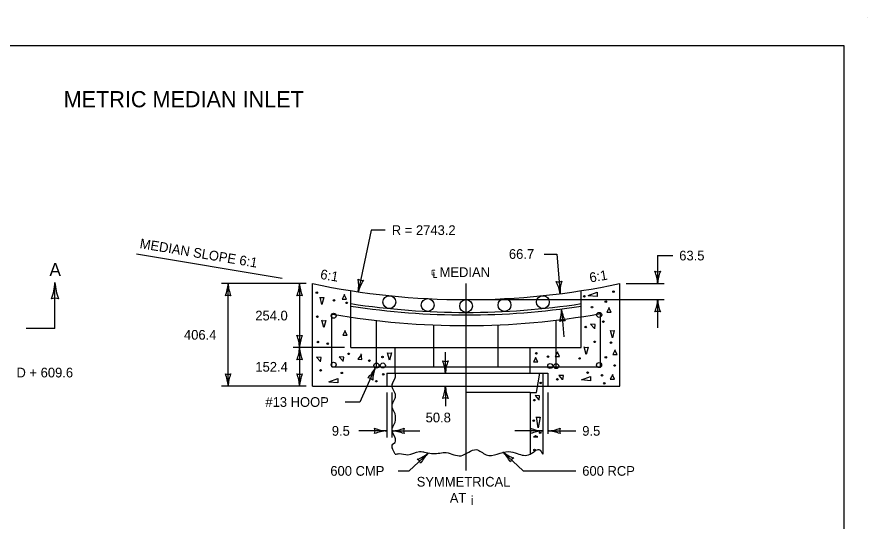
# Model space of a CAD drawing. Extents: x 49991.4 to 50021, y 49987.6 to 50011.4.
# Drawn here: x 50011.64 to 50016.9, y 49996.05 to 49999.18 of the extents above; entities that cross this region are included whole.
import ezdxf

# ---------------------------------------------------------------- set-up
doc = ezdxf.new("R2010")
doc.units = 0
for name, color, linetype in [('Level 1', 7, 'Continuous'), ('Level 2', 7, 'Continuous'), ('Level 3', 7, 'Continuous'), ('Level 4', 7, 'Continuous'), ('Level 5', 7, 'Continuous'), ('Level 6', 7, 'Continuous')]:
    doc.layers.add(name, color=color, linetype=linetype)

msp = doc.modelspace()

# ---------------------------------------------------------------- linework, layer by layer
at = {"layer": 'Level 1'}
for p, q in [((50016.9001, 49999.1756), (50016.9001, 49999.1756)), ((50013.4642, 49996.894), (50013.4642, 49997.5274)), ((50015.3641, 49996.894), (50015.3641, 49997.5274)), ((50013.7017, 49997.1316), (50013.7017, 49997.4839)), ((50015.1266, 49997.1316), (50015.1266, 49997.4839)), ((50014.7555, 49997.3617), (50014.7555, 49997.3617)), ((50013.5829, 49997.0127), (50013.5829, 49997.3383)), ((50015.2454, 49997.0127), (50015.2454, 49997.3419)), ((50013.8595, 49997.0127), (50013.8595, 49997.299)), ((50014.2144, 49997.0126), (50014.2144, 49997.271)), ((50014.612, 49997.0127), (50014.612, 49997.272)), ((50014.9718, 49997.0127), (50014.9718, 49997.3012)), ((50013.7017, 49997.1316), (50015.1266, 49997.1316)), ((50013.9747, 49996.9732), (50013.9747, 49997.1316)), ((50014.81, 49996.9732), (50014.81, 49997.1316)), ((50013.5829, 49997.0127), (50015.2454, 49997.0127)), ((50013.9242, 49996.9732), (50013.9242, 49996.894)), ((50013.9242, 49996.9732), (50013.9748, 49996.9732)), ((50013.9581, 49996.9107), (50013.9747, 49996.9441)), ((50013.9748, 49996.9732), (50014.8891, 49996.9732)), ((50014.8495, 49996.8544), (50014.8694, 49996.9732)), ((50014.8891, 49996.9732), (50014.8891, 49996.4721)), ((50014.8891, 49996.9732), (50014.9192, 49996.9732)), ((50014.9192, 49996.9732), (50014.9192, 49996.894)), ((50013.4642, 49996.894), (50013.9242, 49996.894)), ((50013.9747, 49996.848), (50013.9581, 49996.8813)), ((50014.9192, 49996.894), (50015.3641, 49996.894)), ((50014.81, 49996.8544), (50014.4141, 49996.8544)), ((50014.81, 49996.8544), (50014.81, 49996.4721)), ((50014.81, 49996.8544), (50014.8495, 49996.8544)), ((50013.9581, 49996.7853), (50013.9747, 49996.8187)), ((50013.9747, 49996.7227), (50013.9581, 49996.756)), ((50013.9581, 49996.6375), (50013.9747, 49996.6709)), ((50013.9747, 49996.5749), (50013.9581, 49996.6082)), ((50013.9581, 49996.5347), (50013.9747, 49996.5456)), ((50013.9747, 49996.4721), (50013.9581, 49996.5054))]:
    msp.add_line(p, q, dxfattribs=at)
msp.add_lwpolyline([(49999.3835, 49998.9992), (50016.7501, 49998.9992), (50016.7501, 49987.7988), (49999.3835, 49987.7988)], close=True, dxfattribs=at)
for points in [[(50013.6625, 49997.4608), (50013.6472, 49997.4322), (50013.6742, 49997.4322), (50013.6608, 49997.4592)], [(50015.1692, 49997.4541), (50015.2248, 49997.4744), (50015.2248, 49997.4474), (50015.1692, 49997.4525)], [(50013.5108, 49997.4407), (50013.5344, 49997.4424), (50013.5226, 49997.3986), (50013.5108, 49997.4441)], [(50015.2989, 49997.38), (50015.2838, 49997.3513), (50015.3108, 49997.3513), (50015.2973, 49997.3783)], [(50013.5825, 49997.3385), (50013.5853, 49997.3413), (50013.5855, 49997.3415)], [(50013.5226, 49997.2974), (50013.5462, 49997.2991), (50013.5344, 49997.2553), (50013.5226, 49997.3007)], [(50015.2097, 49997.2485), (50015.213, 49997.2755), (50015.1844, 49997.2772), (50015.2063, 49997.2519)], [(50013.6658, 49997.2367), (50013.6507, 49997.2081), (50013.6776, 49997.2081), (50013.6642, 49997.2351)], [(50015.3073, 49997.2351), (50015.3309, 49997.2368), (50015.3192, 49997.1929), (50015.3073, 49997.2385)], [(50013.7672, 49997.0891), (50013.7452, 49997.0604), (50013.7688, 49997.0587), (50013.7655, 49997.0924)], [(50013.9288, 49997.0968), (50013.9524, 49997.0986), (50013.9406, 49997.0547), (50013.9288, 49997.1002)], [(50014.9804, 49997.1052), (50014.9653, 49997.0767), (50014.9922, 49997.0767), (50014.9787, 49997.1036)], [(50015.1455, 49997.1322), (50015.1691, 49997.134), (50015.1574, 49997.0901), (50015.1455, 49997.1357)], [(50015.336, 49997.117), (50015.3208, 49997.0884), (50015.3478, 49997.0884), (50015.3343, 49997.1153)], [(50013.5142, 49997.0446), (50013.5175, 49997.0716), (50013.4889, 49997.0732), (50013.5108, 49997.048)], [(50013.654, 49997.0462), (50013.6574, 49997.0732), (50013.6287, 49997.0749), (50013.6507, 49997.0497)], [(50014.8456, 49997.0715), (50014.8305, 49997.0429), (50014.8574, 49997.0429), (50014.844, 49997.0698)], [(50013.5648, 49996.9198), (50013.6203, 49996.9401), (50013.6203, 49996.9131), (50013.5648, 49996.9182)], [(50015.0124, 49996.9316), (50015.0158, 49996.9586), (50014.9871, 49996.9602), (50015.009, 49996.935)], [(50015.1288, 49996.9333), (50015.1844, 49996.9536), (50015.1844, 49996.9267), (50015.1288, 49996.9317)], [(50015.3208, 49996.9653), (50015.3057, 49996.9367), (50015.3327, 49996.9367), (50015.3192, 49996.9637)], [(50014.8658, 49996.8069), (50014.8692, 49996.8339), (50014.8405, 49996.8356), (50014.8624, 49996.8103)], [(50014.849, 49996.7007), (50014.8726, 49996.7024), (50014.8608, 49996.6362), (50014.849, 49996.7041)], [(50014.8456, 49996.5872), (50014.8305, 49996.5811), (50014.8574, 49996.5811), (50014.844, 49996.5856)]]:
    msp.add_lwpolyline(points, dxfattribs=at)
for centre in [(50013.4906, 49997.471), (50015.3259, 49997.4777), (50013.5968, 49997.4238), (50013.676, 49997.4086), (50015.1456, 49997.4491), (50015.2787, 49997.4154), (50015.1928, 49997.3817), (50013.4939, 49997.3227), (50015.154, 49997.2587), (50015.2635, 49997.2924), (50013.4973, 49997.1659), (50013.558, 49997.1559), (50015.2096, 49997.1677), (50015.3107, 49997.1626), (50013.6878, 49997.0935), (50014.8489, 49997.0968), (50013.8159, 49997.0514), (50013.8968, 49997.0732), (50014.9202, 49997.076), (50015.1159, 49997.0648), (50015.2787, 49997.0716), (50013.5142, 49996.9907), (50015.3326, 49997.021), (50013.6456, 49996.9755), (50013.9018, 49996.9671), (50014.9787, 49996.9351), (50015.1658, 49996.9772), (50015.2551, 49996.9604), (50013.8594, 49996.924), (50014.8759, 49996.9131), (50015.2686, 49996.9115), (50014.8355, 49996.807), (50014.8321, 49996.6806), (50014.8725, 49996.6064), (50014.8372, 49996.4985)]:
    msp.add_circle(centre, 0.00476, dxfattribs=at)
for centre, major_axis, ratio, start_param, end_param in [((50014.4141, 50002.0379), (0, -4.6095), 0.99996, 6.075605, 6.490769), ((50014.4141, 50002.0379), (0, -4.6886), 0.99996, 6.130631, 6.435739), ((50014.4141, 50002.0323), (0, -4.6985), 0.99996, 6.130999, 6.435415), ((50014.4065, 50002.0353), (0, -4.7678), 0.99996, 6.110622, 6.460063), ((50013.9454, 49996.9587), (0, -0.0328), 0.99996, 1.107175, 2.034314), ((50013.9874, 49996.896), (0, 0.0328), 0.99996, 1.107223, 2.034348), ((50013.9454, 49996.8334), (0, -0.0328), 0.99996, 1.107175, 2.034314), ((50013.9874, 49996.7707), (0, 0.0328), 0.99996, 1.107223, 2.034348), ((50013.9454, 49996.6968), (0, -0.0579), 0.565735, 1.107175, 2.034314), ((50013.9874, 49996.6229), (0, 0.0328), 0.99996, 1.107223, 2.034348), ((50013.9454, 49996.5602), (0, -0.0328), 0.99996, 1.107175, 2.034314), ((50013.9874, 49996.5201), (0, 0.0328), 0.99996, 1.107223, 2.034348)]:
    msp.add_ellipse(centre, major_axis=major_axis, ratio=ratio, start_param=start_param, end_param=end_param, dxfattribs=at)
for centre, major_axis in [((50013.9392, 49997.4129), (0, 0.0396)), ((50014.1767, 49997.3949), (0, 0.0396)), ((50014.4141, 49997.3888), (0, 0.0396)), ((50014.6516, 49997.3949), (0, 0.0396)), ((50014.8891, 49997.4129), (0, 0.0396)), ((50013.5949, 49997.329), (0, 0.0156)), ((50015.2381, 49997.3341), (0, 0.0156)), ((50013.5949, 49997.0256), (0, 0.0156)), ((50015.2364, 49997.024), (0, 0.0156)), ((50013.8595, 49997.0206), (0, 0.0156)), ((50013.8991, 49997.0214), (0, 0.0156)), ((50014.9343, 49997.018), (0, 0.0156)), ((50014.9718, 49997.0172), (0, 0.0156))]:
    msp.add_ellipse(centre, major_axis=major_axis, ratio=0.99996, dxfattribs=at)
msp.add_spline([(50013.9747, 49996.4721), (50014.0004, 49996.4761), (50014.0537, 49996.4698), (50014.1257, 49996.4886), (50014.2104, 49996.4761), (50014.2917, 49996.4823), (50014.3826, 49996.4636), (50014.4766, 49996.5011), (50014.5385, 49996.4693), (50014.6771, 49996.4886), (50014.7303, 49996.4761), (50014.81, 49996.4721), (50014.865, 49996.5011), (50014.8891, 49996.4721)], degree=3, dxfattribs=at)
at = {"layer": 'Level 2'}
msp.add_line((50013.2773, 49997.5587), (50012.376, 49997.7095), dxfattribs=at)
at = {"layer": 'Level 3'}
for p, q in [((50013.8275, 49997.858), (50013.7472, 49997.4769)), ((50013.9145, 49997.858), (50013.8275, 49997.858)), ((50014.898, 49997.7104), (50014.9747, 49997.7104)), ((50014.9747, 49997.7104), (50014.9952, 49997.4652)), ((50015.5989, 49997.7008), (50015.5989, 49997.5274)), ((50015.5989, 49997.7008), (50015.6925, 49997.7008)), ((50013.4242, 49997.5274), (50012.9021, 49997.5274)), ((50012.9421, 49996.894), (50012.9421, 49997.5274)), ((50013.3839, 49997.5274), (50013.3839, 49997.1318)), ((50015.4041, 49997.5274), (50015.6389, 49997.5274)), ((50014.5141, 49997.4284), (50015.6389, 49997.4284)), ((50015.5989, 49997.4284), (50015.5989, 49997.255)), ((50015.0035, 49997.3709), (50015.0187, 49997.1981)), ((50013.6617, 49997.1316), (50013.3439, 49997.1316)), ((50013.3839, 49997.1318), (50013.3839, 49996.894)), ((50014.2861, 49996.9732), (50014.2861, 49997.1032)), ((50013.8524, 49997.0068), (50013.7574, 49996.7954)), ((50013.4242, 49996.894), (50012.9021, 49996.894)), ((50014.2861, 49996.894), (50014.2861, 49996.7697)), ((50013.9242, 49996.854), (50013.9242, 49996.5769)), ((50013.954, 49996.854), (50013.954, 49996.5769)), ((50014.9192, 49996.854), (50014.9192, 49996.5994)), ((50013.7574, 49996.7954), (50013.667, 49996.7954)), ((50013.9242, 49996.6169), (50013.7508, 49996.6169)), ((50013.954, 49996.6169), (50014.1274, 49996.6169)), ((50014.8891, 49996.6169), (50014.7157, 49996.6169)), ((50014.9192, 49996.6169), (50015.0926, 49996.6169)), ((50014.1797, 49996.48), (50014.0619, 49996.3694)), ((50014.1479, 49996.4889), (50014.1479, 49996.4865)), ((50014.6405, 49996.4878), (50014.7666, 49996.3694)), ((50013.994, 49996.3694), (50014.0619, 49996.3694)), ((50014.7666, 49996.3694), (50015.0926, 49996.3694))]:
    msp.add_line(p, q, dxfattribs=at)
for centre, radius, start, end in [((50013.1618, 49997.5366), 0.2223, 337.456, 357.6395), ((50013.6166, 49997.5389), 0.233, 182.8273, 202.0772), ((50013.7737, 49997.6024), 0.0548, 240.2517, 275.974), ((50013.5172, 49997.5136), 0.233, 350.9402, 10.19), ((50013.9627, 49997.4222), 0.2223, 145.5689, 165.7524), ((50014.9845, 49997.593), 0.0548, 256.9218, 292.6442), ((50014.7642, 49997.4343), 0.233, 7.6103, 26.8602), ((50015.2173, 49997.4746), 0.2223, 162.239, 182.4225), ((50013.3839, 49997.3992), 0.0548, 72.1388, 107.8612), ((50013.3839, 49997.2598), 0.0548, 252.1388, 287.8612), ((50013.1512, 49997.1201), 0.233, 2.8273, 22.0772), ((50013.606, 49997.1224), 0.2223, 157.456, 177.6395), ((50013.1618, 49997.1408), 0.2223, 337.456, 357.6395), ((50013.6166, 49997.1431), 0.233, 182.8273, 202.0772), ((50013.3839, 49997.0034), 0.0548, 72.1388, 107.8612), ((50013.6536, 49997.1062), 0.2223, 313.2474, 333.4309), ((50014.0694, 49996.9218), 0.233, 158.6187, 177.8686), ((50013.3839, 49997.0222), 0.0548, 252.1388, 287.8612), ((50013.1512, 49996.8825), 0.233, 2.8273, 22.0772), ((50013.606, 49996.8848), 0.2223, 157.456, 177.6395), ((50013.7998, 49996.8898), 0.0548, 47.9302, 83.6526), ((50013.9334, 49996.839), 0.2223, 247.456, 267.6395), ((50013.796, 49996.6169), 0.0548, 342.1388, 17.8612), ((50013.9425, 49996.8496), 0.233, 272.8273, 292.0772), ((50014.0822, 49996.6169), 0.0548, 162.1388, 197.8612), ((50014.8983, 49996.839), 0.2223, 247.456, 267.6395), ((50014.7609, 49996.6169), 0.0548, 342.1388, 17.8612), ((50014.9077, 49996.8496), 0.233, 272.8273, 292.0772), ((50015.0474, 49996.6169), 0.0548, 162.1388, 197.8612), ((50013.9357, 49996.3842), 0.233, 92.8273, 112.0772), ((50013.9448, 49996.3948), 0.2223, 67.456, 87.6395), ((50014.9006, 49996.3842), 0.233, 92.8273, 112.0772), ((50014.91, 49996.3948), 0.2223, 67.456, 87.6395)]:
    msp.add_arc(centre, radius, start, end, dxfattribs=at)
for centre, major_axis, start_param, end_param in [((50015.5989, 49997.6556), (0, -0.0548), 5.971449, 6.594922), ((50015.3662, 49997.5159), (0, 0.233), 4.761735, 5.097708), ((50015.821, 49997.5182), (0, 0.2223), 1.177329, 1.529598), ((50011.5748, 49997.5466), (0, -0.2964), 1.177329, 1.529598), ((50012.1813, 49997.5497), (0, -0.3107), 4.761735, 5.097708), ((50012.72, 49997.5366), (0, -0.2223), 1.177329, 1.529598), ((50013.1748, 49997.5389), (0, -0.233), 4.761735, 5.097708), ((50011.871, 49997.3634), (0, 0.073), 5.971449, 6.594922), ((50012.9421, 49997.3992), (0, 0.0548), 5.971449, 6.594922), ((50015.3768, 49997.4376), (0, -0.2223), 1.177329, 1.529598), ((50015.8316, 49997.4399), (0, -0.233), 4.761735, 5.097708), ((50014.7815, 49997.3592), (0, -0.2223), 1.271255, 1.623523), ((50015.2341, 49997.4042), (0, -0.233), 4.85566, 5.191633), ((50015.5989, 49997.3002), (0, 0.0548), 5.971449, 6.594922), ((50015.0155, 49997.2432), (0, 0.0548), 6.065374, 6.688847), ((50014.2861, 49997.1014), (0, -0.0548), 5.971449, 6.594922), ((50014.0534, 49996.9617), (0, 0.233), 4.761735, 5.097708), ((50014.5082, 49996.964), (0, 0.2223), 1.177329, 1.529598), ((50012.9421, 49997.0222), (0, -0.0548), 5.971449, 6.594922), ((50012.7094, 49996.8825), (0, 0.233), 4.761735, 5.097708), ((50013.1642, 49996.8848), (0, 0.2223), 1.177329, 1.529598), ((50014.064, 49996.9032), (0, -0.2223), 1.177329, 1.529598), ((50014.5188, 49996.9055), (0, -0.233), 4.761735, 5.097708), ((50014.2861, 49996.7658), (0, 0.0548), 5.971449, 6.594922), ((50014.0372, 49996.6507), (0, -0.2223), 0.343529, 0.695798), ((50014.3447, 49996.3154), (0, 0.233), 0.786342, 1.122315), ((50014.486, 49996.3279), (0, 0.2223), 5.162843, 5.515112), ((50014.7865, 49996.6694), (0, -0.233), 5.605656, 5.941629), ((50014.0848, 49996.3939), (0, 0.0548), 5.137648, 5.761121), ((50014.7363, 49996.4026), (0, 0.0548), 0.532185, 1.155658)]:
    msp.add_ellipse(centre, major_axis=major_axis, ratio=0.99996, start_param=start_param, end_param=end_param, dxfattribs=at)
at = {"layer": 'Level 4'}
msp.add_line((50013.9242, 49996.894), (50014.9192, 49996.894), dxfattribs=at)
at = {"layer": 'Level 5'}
msp.add_line((50014.4141, 49996.3725), (50014.4141, 49997.5284), dxfattribs=at)
at = {"layer": 'Level 6'}
for q in [(50011.871, 49997.5344), (50011.6929, 49997.2494)]:
    msp.add_line((50011.871, 49997.2494), q, dxfattribs=at)

# ---------------------------------------------------------------- texts
at = {"layer": 'Level 2'}
for s, height, p in [('METRIC MEDIAN INLET', 0.1, (50011.9245, 49998.6175)), ('R = 2743.2', 0.06, (50013.9545, 49997.828)), ('66.7', 0.06, (50014.679, 49997.6804)), ('63.5', 0.06, (50015.7325, 49997.6708)), ('A', 0.08, (50011.8367, 49997.5744)), ('℄ MEDIAN', 0.06, (50014.1954, 49997.5684)), ('254.0', 0.06, (50013.1101, 49997.2997)), ('406.4', 0.06, (50012.6689, 49997.1807)), ('152.4', 0.06, (50013.1107, 49996.983)), ('D + 609.6', 0.06, (50011.6329, 49996.9475)), ('#13 HOOP', 0.06, (50013.1726, 49996.7654)), ('50.8', 0.06, (50014.1638, 49996.6697)), ('9.5', 0.06, (50013.5834, 49996.5869)), ('9.5', 0.06, (50015.1326, 49996.5869)), ('600 CMP', 0.06, (50013.5742, 49996.3394)), ('600 RCP', 0.06, (50015.1326, 49996.3394)), ('SYMMETRICAL', 0.06, (50014.1086, 49996.2725)), ('AT ¡', 0.06, (50014.3133, 49996.1725))]:
    msp.add_text(s, height=height, dxfattribs=at).set_placement(p)
for s, height, rotation, p in [('MEDIAN SLOPE 6:1', 0.059999, 350.5028, (50012.3923, 49997.7473)), ('6:1', 0.06, 350.5028, (50013.5088, 49997.5572)), ('6:1', 0.06, 9.4972, (50015.1822, 49997.5342))]:
    msp.add_text(s, height=height, rotation=rotation, dxfattribs=at).set_placement(p)

doc.saveas('drawing.dxf')
